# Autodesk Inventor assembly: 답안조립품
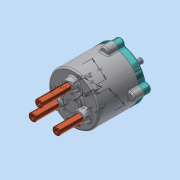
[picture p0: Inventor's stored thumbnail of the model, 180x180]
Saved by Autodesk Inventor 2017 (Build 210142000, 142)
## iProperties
Part Number: 답안조립품
Material: 일반
Document SubType Name: Assembly
Designer: MRC
Author: MRC
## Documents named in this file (14)
- C:\Users\MRC\Desktop\610708V1005\답안조립품.iam
- C:\Users\MRC\Desktop\610708V1005\본체.ipt
- C:\Users\MRC\Desktop\610708V1005\가변스프링1.ipt
- C:\Users\MRC\Desktop\610708V1005\가변스프링2.ipt
- C:\Users\MRC\Desktop\610708V1005\가변스프링3.ipt
- C:\Users\MRC\Desktop\610708V1005\멈춤링 10 x 1.ipt
- C:\Users\MRC\Desktop\610708V1005\멈춤링 22 x 1.2.ipt
- C:\Users\MRC\Desktop\610708V1005\메인 축.ipt
- C:\Users\MRC\Desktop\610708V1005\베어링 NA 4900.ipt
- C:\Users\MRC\Desktop\610708V1005\볼트 M5.ipt
- C:\Users\MRC\Desktop\610708V1005\슬라이드 축.ipt
- C:\Users\MRC\Desktop\610708V1005\오일실.ipt
- C:\Users\MRC\Desktop\610708V1005\커버.ipt
- C:\Users\MRC\Desktop\610708V1005\판캠.ipt
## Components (3 placed, 3 different names)
1. 가변스프링1:1
2. 가변스프링2:1
3. 가변스프링3:1
